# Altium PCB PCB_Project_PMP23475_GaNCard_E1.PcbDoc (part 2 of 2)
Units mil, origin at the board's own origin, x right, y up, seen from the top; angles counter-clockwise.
Board outline 1635 x 1330 mil, 6 copper layers (Top Layer, MidLayer1, MidLayer2, MidLayer3, MidLayer4, Bottom Layer), stack 78 mil thick; 80 components, 70 nets, 296 pads, 209 vias.
Unrouted connection lines stored in the file: 3.
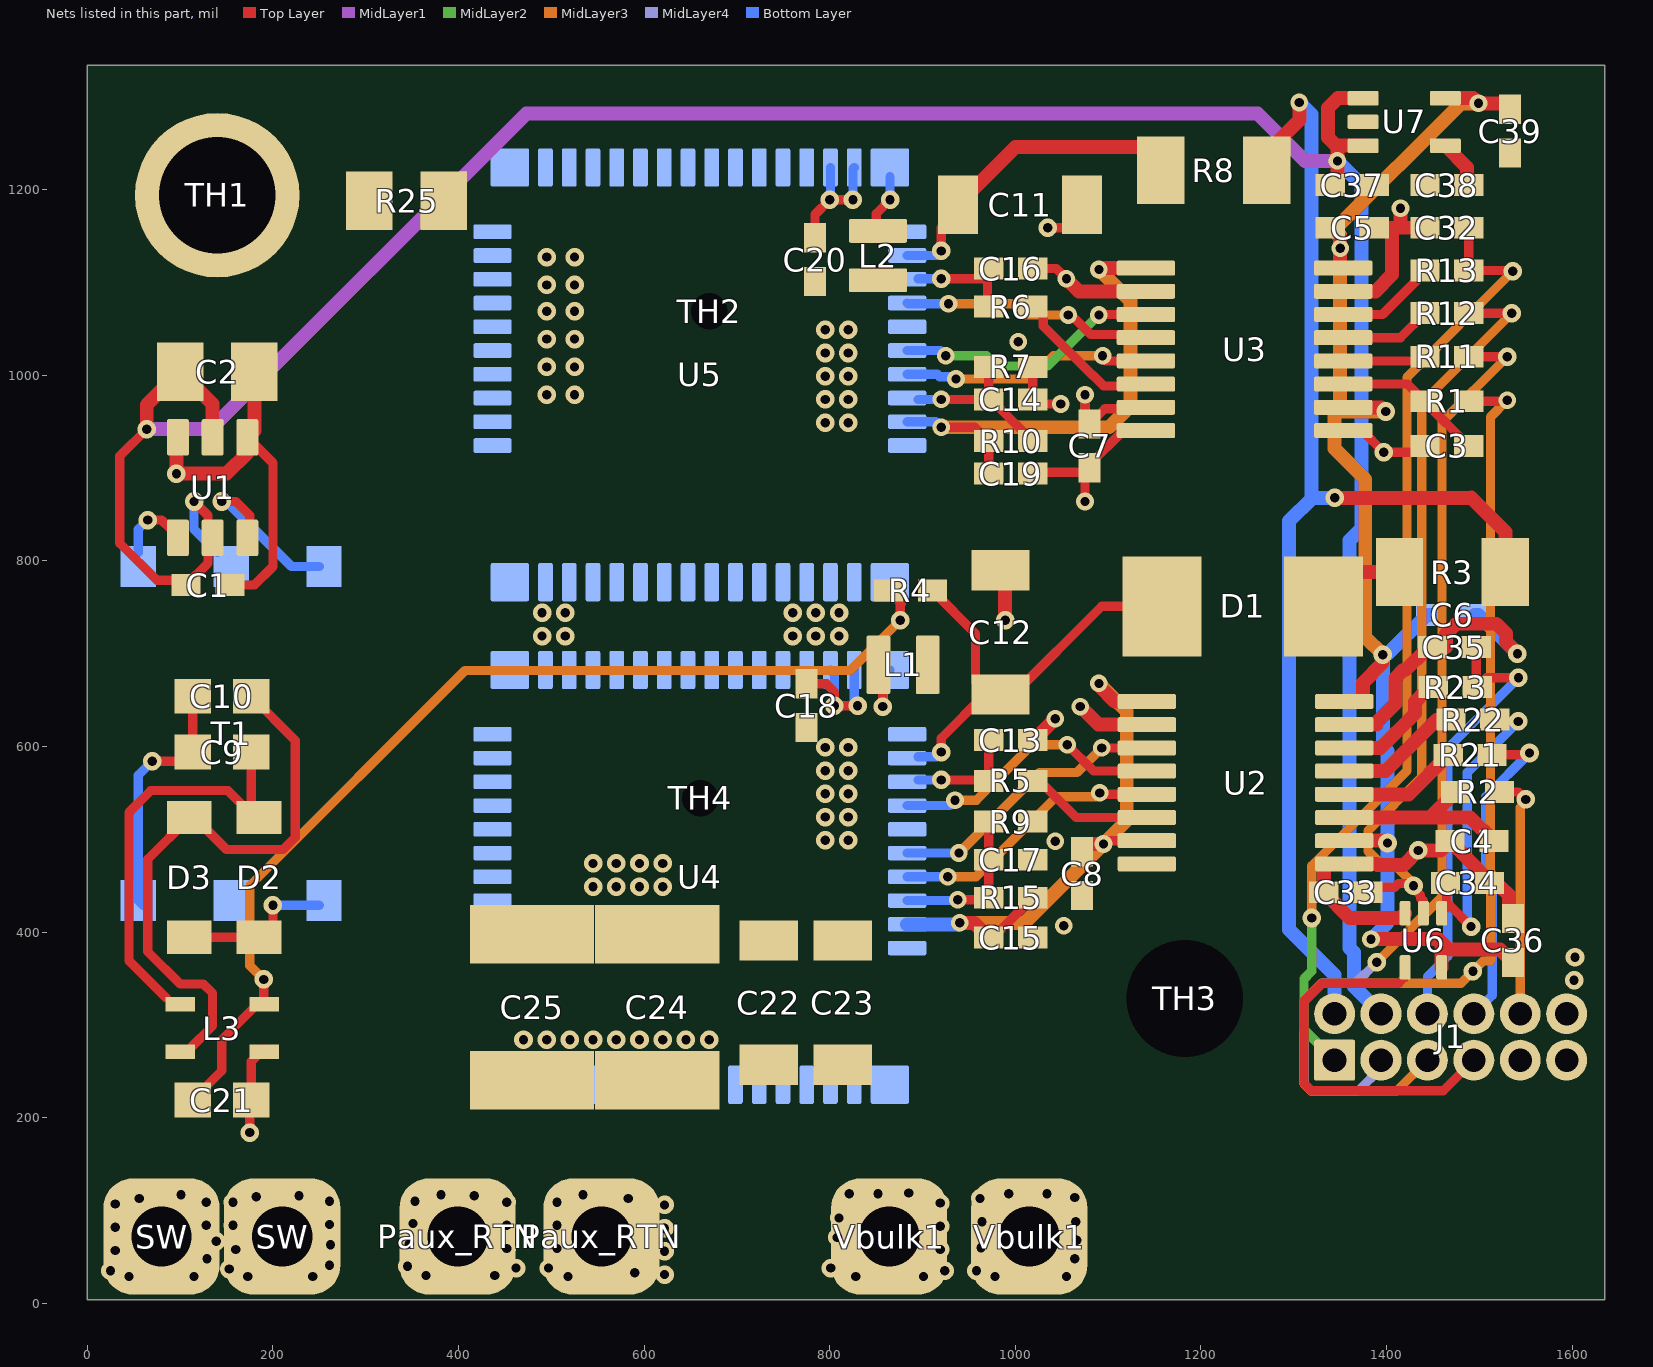
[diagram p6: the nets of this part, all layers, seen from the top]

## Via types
v1: diameter 20, hole 10, Top Layer to Bottom Layer, 174 vias
v2: diameter 19, hole 10, Top Layer to Bottom Layer, tented both sides, 35 vias

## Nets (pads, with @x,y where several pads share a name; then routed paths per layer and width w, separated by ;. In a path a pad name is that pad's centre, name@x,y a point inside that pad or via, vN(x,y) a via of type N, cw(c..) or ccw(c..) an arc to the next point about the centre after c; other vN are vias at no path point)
3.3V: C5.1 C6.1 C36.1 C39.2 U2.10 U2.16 U3.10 U3.16 U6.5 U7.5 | length 1624.1
  Top Layer w15: C5.1@1339.38,1159 1350,1148.38 v2(1350,1137) 1350,1118.8 U3.16@1353.3,1115.5 ; U3.10@1353.3,965.5 1394.5,965.5 v1(1399,961) ; U2.10@1354.3,498.5 1398.5,498.5 v1(1401,496) ; U2.16@1354.3,648.5 1373.85,648.5 1374.43,649.07 1374.43,668.63 1395.04,689.24 1395.04,698.04 v1(1396,699) ; v2(1383.15,392.23) 1383.48,392.56 1455.89,392.56 1467.14,381.31 1522.07,381.31 C36.1@1536,367.38 ; U6.5@1459.37,362 1459.37,389.08 ; U7.5@1463.29,1298.59 1493.41,1298.59 v2(1499,1293) 1526.62,1293 C39.2@1533,1286.62
  MidLayer3 w15: v1(1396,699) 1377,718 1377,888 1344,921 1344,960 1345,961 ; v1(1399,961) 1345,961 ; v2(1499,1293) 1480,1293 1344,1157 1350,1151 v2(1350,1137) 1350,966 1345,961
  Bottom Layer w15: v2(1383.15,392.23) 1401,410.08 v1(1401,496) 1401,595 1396,600 v1(1396,699) 1396.96,699.96 1401.66,699.96 1443.44,741.74 C6.1@1447.38,741.74
5V: C1.1 C2.1 C37.1 J1.4 T1.5 U1.2 U1.5 U7.1 U7.3 | length 3063
  Top Layer w10: v1(64,942) 35,913 35,819 75,779 C1.1@100,779 ; C1.1@106.38,774 130,797.62 U1.2@130,819 ; v1(115,864) 130,849 U1.2@130,839
  Top Layer w15: v1(64,942) 64,968 C2.1@100,1004 C2.1@101.5,1002.5 ; C2.1@118.5,985.5 135,969 U1.5@135,933.13 ; C37.1@1339.38,1205 1347,1212.62 v2(1347,1231) 1347,1243 1351.41,1247.41 ; U7.3@1374.71,1247.41 1351.41,1247.41 ; U7.1@1374.71,1298.59 1347.59,1298.59 1337,1288 1337,1256 1345.59,1247.41 1351.41,1247.41
  MidLayer1 w15: v1(64,942) 133,942 473,1282 1261,1282 1312,1231 v2(1347,1231)
  Bottom Layer w10: v1(115,864) 115,834 T1.5@140,809
  Bottom Layer w15: v2(1347,1231) 1373,1205 1373,835 1360.15,822.15 1360.15,382.7 1365,377.85 1365,341.27 1394,312.27 J1.4@1394,312
5V_H: C8.1 C15.2 R15.1 U2.1 U2.7 U4.51 | length 682.1
  Top Layer w10: C15.2@971.38,394 975.51,394 998.32,416.81 998.43,416.81 R15.1@1018.62,437 ; v2(1095,495) 1098.5,498.5 U2.7@1141.7,498.5
  Top Layer w15: v2(940,410) 955.38,410 C15.2@971.38,394 ; C8.1@1072,486.62 1080.38,495 v2(1095,495) ; v2(1090,668) 1090,665.55 1107.05,648.5 U2.1@1141.7,648.5
  MidLayer3 w15: v2(940,410) 1010,410 v2(1095,495) 1120,520 1120,638 v2(1090,668)
  Bottom Layer w10: v2@938.41,408.41 v2(940,410)
  Bottom Layer w15: U4.51@883.43,408.41 v2@938.41,408.41
5V_L: C7.2 C19.2 R10.1 U3.1 U3.7 U5.51 | length 649.9
  Top Layer w10: v2@925,944 956.38,944 R10.1@971.38,929 971.38,895.38 C19.2@970,894 ; C7.2@1075,954 v2(1075,979) ; C7.2@1080,947.62 1096.38,964 U3.7@1110,964
  Top Layer w15: v2(1090,1114) 1091.5,1115.5 U3.1@1140.7,1115.5
  MidLayer3 w10: 1075,944 v2(1075,979)
  MidLayer3 w15: v2(920,944) 1075,944 1101,944 1124,967 1124,1080 v2(1090,1114)
  Bottom Layer w10: U5.51@883.43,949.91 914.09,949.91 v2(920,944)
12V: J1.2 R3.1 R8.1 | length 1392.4
  Top Layer w15: R8.1@1271.09,1221 1271.09,1229 1260,1229 1306,1275 v2(1306,1294) v2@1306,1292.09 ; v1(1344,868) 1491.38,868 ; 1491.19,868.19 1491.38,868 ; R3.1@1528.09,788 1528.09,831.29 1491.38,868
  Bottom Layer w15: v2(1306,1294) 1319,1281 1319,867 1320,868 ; J1.2@1344,312 1344,353.9 1295,402.9 1295,843 1320,868 ; v1(1344,868) 1320,868
AGND: C1.2 C2.2 C3.2 C4.2 C5.2 C6.2 C32.2 C33.2 C34.2 C35.2 C36.2 C37.2 C38.2 C39.1 J1.9 J1.11 J1.12 U1.4 U1.6 U2.9 U2.15 U3.9 U3.15 U6.3 U7.2 | length 1440.8
  Top Layer w10: C1.2@155,774 180,774 200,794 200,905.54 U1.4@172.63,932.9 ; U3.9@1353.3,940.5 1373.5,940.5 v1(1397,917) 1434.38,917 C3.2@1441.38,924
  Top Layer w15: U1.6@97.6,933.13 96,931.54 v1(96,894) 150.12,894 172.63,916.51 172.63,932.9 180,940.27 C2.2@180,1004 ; U3.15@1353.3,1090.5 1387.95,1090.5 1406,1108.55 1406,1159 ; U2.15@1354.3,623.5 1388.95,623.5 1388.95,625.63 1409.45,646.13 1409.45,673.95 1418.24,682.74 1421.18,682.74 1441.13,702.69 1445.07,702.69 C35.2@1449.38,707 1464.19,707 1464.19,721.22 1475.28,732.31 1517.96,732.31 1528.57,721.7 1528.57,712.43 v1(1541,700) ; C5.2@1386.62,1160 1387.62,1159 1415,1159 ; v2(1415,1180) 1415,1159 ; U6.3@1420,420.27 1414.96,415.23 1360.15,415.23 C33.2@1332.38,443 1332.38,472.93 1332.95,473.5 1388.95,473.5 1389.95,472.5 1418.5,472.5 v1(1434,488) 1458.38,488 C4.2@1468.38,498 1504.62,461.76 C34.2@1504.62,453 ; C32.2@1440.38,1160 C32.2@1441.38,1159 1415,1159 ; C34.2@1510.62,453 1514.93,448.69 1522.9,448.69 1531.69,439.9 1531.69,418.93 C36.2@1536,414.62
  Bottom Layer w15: C6.2@1494.62,741.74 1499.26,741.74 v1(1541,700)
  other v1: 1602,348 1603,373
FAULT_HS: U2.4 U4.46 | length 297.3
  Top Layer w10: v2(1056,602) 1084.5,573.5 U2.4@1141.7,573.5
  MidLayer3 w10: v2(935,542) 958,542 1018,602 v2(1056,602)
  Bottom Layer w10: U4.46@883.43,536.36 929.36,536.36 v2(935,542)
FAULT_LS: U3.4 U5.46 | length 272.7
  Top Layer w10: v2(1057,1065) 1060.3,1065 1081.3,1044 1137.2,1044 U3.4@1140.7,1040.5
  MidLayer3 w10: v2(928,1077) 997.78,1077 1009.78,1065 v2(1057,1065)
  Bottom Layer w10: U5.46@883.43,1077.86 884.28,1077 v2(928,1077)
GaN_F: J1.7 U6.4 | length 424.4
  Top Layer w10: U6.4@1420,367.32 1419.09,366.41 1419.09,350.91 1413.24,345.05 1330.31,345.05 1310.95,325.69 1310.95,236.56 1318.56,228.95 1460.95,228.95 J1.7@1494,262
HS_FAULT: C34.1 R22.2 U6.1 | length 348.6
  Top Layer w10: C34.1@1457.38,453 1458.14,453 1464.95,446.19 1464.95,432.05 1468.05,428.95 ; U6.1@1459.37,420.27 1459.37,425.28 1460.28,426.19 1465.29,426.19 1468.05,428.95 ; v1(1491,406) 1468.05,428.95 ; R22.2@1516.62,629 1518.62,627 v1(1542,627)
  Bottom Layer w10: v1@1487,404 1487,572 v1(1542,627)
HS_PWM: J1.10 R2.1 | length 254
  Top Layer w10: R2.1@1521.62,551 1542,551 v1(1550,543)
  MidLayer3 w10: J1.10@1544,312 1544,534.29
HS_TEMP: J1.8 R21.2 | length 352.9
  Top Layer w10: R21.2@1513.62,591 1552,591 v1(1554,593)
  Bottom Layer w10: J1.8@1494,312 1514,332 1514,462 1507,469 1507,546 v1(1554,593)
HS_ZVS: C35.1 J1.6 R23.2 | length 493.2
  Top Layer w10: R23.2@1496.62,665 C35.1@1496.62,707 ; R23.2@1497.62,664 1507.64,674.02 v1(1542.04,674.02)
  Bottom Layer w10: J1.6@1444,312 1444,352 1466,374 1466,597.98 v1(1542.04,674.02)
HVBUS: C22.1 C23.1 C24.1 C25.1 U4.2 U4.3 U4.4 U4.5 U4.6 U4.7 U4.8 U4.9 U4.10 U4.11 U4.12 U4.13 U4.14 U4.15 Vbulk1.1
  other v1: 828,29 901,29 978,29 1055,29 924,35 958,35 801,38 1064,48 919,58 963,60 1066,68 808,71 919,83 964,88 1065,88 810,92 919,108 962,113 1064,114 821,118 852,118 993,118 1034,118 885,119 470,284 495,284 520,284 545,284 570,284 595,284 620,284 645,284 670,284
ISO_12V_H: C21.1 L3.2 R4.1 | length 1117.5
  Top Layer w10: C21.1@113.5,219 145,250.5 145,284 L3.2@180,319 ; L3.2@190,324 v1(190,349) ; R4.1@863.38,768 877.31,754.07 876,752.76 v1(876,736.02)
  MidLayer3 w10: v1(190,349) 175,364 175,450 407,682 821.98,682 v1(876,736.02)
LS_FAULT: C33.1 R12.2 U6.2 | length 844.3
  Top Layer w10: C33.1@1379.62,443 1384.94,448.32 1408.88,448.32 1412.88,452.32 1426.68,452.32 v1(1429,450) 1429,447.29 1436.63,439.66 1436.63,436.63 1439.69,433.58 U6.2@1439.69,420.27 ; R12.2@1488.62,1067 v1(1535,1067)
  MidLayer3 w10: v1(1429,450) 1429,452 1406,475 1392.3,475 1379.96,487.35 1379.96,509.33 1438,567.37 1438,970 v1(1535,1067)
LS_PWM: J1.5 R1.1 | length 1111.3
  Top Layer w10: R1.1@1488.62,972 1529,972 v2(1530,973)
  MidLayer3 w10: J1.5@1444,262 1410.95,228.95 1318.56,228.95 1310.95,236.56 1310.95,325.69 1330.31,345.05 1480.24,345.05 v1(1493,357.81) 1504.05,368.86 1512,368.86 1512,955 v2(1530,973)
LS_TEMP: J1.3 R11.2 | length 1041.9
  Top Layer w10: R11.2@1488.62,1020 v1(1530,1020)
  MidLayer3 w10: v1(1389.41,367.51) 1459.7,437.8 1459.7,949.7 v1(1530,1020)
  MidLayer4 w10: v1(1389.41,367.51) 1367.05,345.15 1330.41,345.15 1310.95,325.69 1310.95,236.56 1318.56,228.95 1369.44,228.95 1394,253.51 J1.3@1394,262
LS_ZVS: C32.1 J1.1 R13.2 | length 1050.7
  Top Layer w10: C32.1@1488.62,1159 R13.2@1488.62,1113 1535,1113 v1(1536,1112)
  MidLayer2 w10: v1(1319.5,415.19) 1319.5,358.04 1310.95,349.49 1310.95,295.05 J1.1@1344,262
  MidLayer3 w10: v1(1319.5,415.19) 1319.5,471.5 1422,574 1422,998 v1(1536,1112)
NC1: R25.2 TH1.1
NC2: TH2.1
NC3: TH3.1
NC4: TH4.1
NCT1: T1.2
NCU51: U4.1
NCU61: U5.1
NCU516: U4.16
NCU527: U4.27
NCU543: U4.43
NCU547: U4.47
NCU552: U4.52
NCU616: U5.16
NCU627: U5.27
NCU643: U5.43
NCU647: U5.47
NCU652: U5.52
NetC3_1: C3.1 R1.2 U3.11 | length 163.3
  Top Layer w10: U3.11@1353.3,990.5 1422.88,990.5 R1.2@1441.38,972 1441.38,971.24 C3.1@1488.62,924
NetC4_1: C4.1 R2.2 U2.11 | length 210.8
  Top Layer w15: U2.11@1354.3,523.5 1446.88,523.5 ; R2.2@1474.38,551 1446.88,523.5 ; C4.1@1515.62,498 1490.12,523.5 1446.88,523.5
NetC9_1: C9.1 D2.1 L3.3 | length 444.8
  Top Layer w10: L3.3@85,329 45,369 45,529 68.48,552.48 151.52,552.48 D2.1@176.5,527.5 ; C9.1@176.5,594 D2.1@176.5,527.5 ; D2.1@185,523.47 180.53,523.47 D2.1@176.5,527.5
NetC9_2: C9.2 C10.1 T1.3 | length 264.7
  Top Layer w10: v1(70,584) C9.2@110,584 ; C9.2@110,594 113.5,597.5 C10.1@113.5,654
  Bottom Layer w10: T1.3@60,429 T1.3@55,434 55,569 v1(70,584)
NetC10_2: C10.2 D3.2 L3.4 | length 601.4
  Top Layer w10: L3.4@110,274 135,299 135,334 125,344 100,344 65,379 65,478.47 D3.2@110,523.47 ; D3.2@130,509 150,489 211,489 224,502 224,606.5 C10.2@176.5,654
NetC11_1: C11.1 R8.2 U5.44 | length 349.6
  Top Layer w10: v1@922.5,1131.5 v1(920,1134) 920,1159 C11.1@930,1169 ; C11.1@938.07,1175.93 C11.1@938.07,1184
  Top Layer w15: C11.1@938.07,1184 1000.07,1246 1141,1246 1141,1236.91 R8.2@1156.91,1221
  Bottom Layer w10: U5.44@883.43,1129.04 915.04,1129.04 v1(920,1134)
NetC12_1: C12.1 D1.1 R4.2 U4.44 | length 529
  Top Layer w10: R4.2@910.62,768 957,721.62 957,669 969.93,656.07 C12.1@984,656.07 ; v1(920,594) 920,609 967.07,656.07 C12.1@984,656.07 ; D1.1@1129.99,723 D1.1@1157.99,751 1093,751 998.07,656.07 C12.1@984,656.07
  Bottom Layer w10: U4.44@895,589 915,589 v1(920,594)
NetC13_2: C13.2 R5.1 U4.45 | length 119.8
  Top Layer w10: v1(920,564) 970.38,564 R5.1@971.38,565 ; R5.1@971.38,563 R5.1@971.38,565 ; C13.2@971.38,606 R5.1@971.38,565
  Bottom Layer w10: U4.45@895,564 v1(920,564)
NetC14_2: C14.2 R7.2 R10.2 U5.50 | length 179.6
  Top Layer w10: v2(920,974) C14.2@971.38,974 ; R7.2@975,1009 971.38,1005.38 C14.2@971.38,974 ; R10.2@1018.62,929 975,972.62 975,974 C14.2@971.38,974
  Bottom Layer w10: U5.50@895,974 v2(920,974)
NetC16_2: C16.2 R6.2 U5.45 | length 116.6
  Top Layer w10: v1(920,1104) C16.2@970,1104 ; R6.2@970,1074 C16.2@970,1104 ; C16.2@971.38,1115 971.38,1105.38 C16.2@970,1104
  Bottom Layer w10: U5.45@895,1104 v1(920,1104)
NetC17_2: C17.2 R9.2 R15.2 U4.50 | length 171.2
  Top Layer w10: v2(938,435) 969.38,435 R15.2@971.38,437 C17.2@971.38,478 R9.2@971.38,519
  Bottom Layer w10: U4.50@883.43,434 937,434 v2(938,435)
NetC18_1: C18.1 U4.40 U4.41 | length 148.7
  Top Layer w10: C18.1@775,667.62 796.38,667.62 805,659 v1@805,649 ; v1(805,644) v1(830,644)
  Bottom Layer w10: U4.40@800.75,682.43 805,678.17 v1(805,644) ; U4.41@826.34,682.43 826.34,647.66 v1(830,644)
NetC20_1: C20.1 U5.40 U5.41 | length 140.1
  Top Layer w10: C20.1@784.19,1148.25 784.19,1173.19 v1(800,1189) 820,1189 v1@825,1184
  Bottom Layer w10: v1(800,1189) 800.75,1189.75 U5.40@800.75,1223.92 ; v1@825,1194 825,1222.58 U5.41@826.34,1223.92
  other v1: 825,1189
NetC38_1: C38.1 U7.4 | length 52.9
  Top Layer w15: U7.4@1463.29,1247.41 1486.62,1224.08 1486.62,1207 C38.1@1488.62,1205
NetD1_2: D1.2 R3.2 | length 97.2
  Top Layer w15: D1.2@1332.01,751 1369.01,788 R3.2@1413.91,788
NetD2_2: D2.2 D3.1 T1.1 | length 157.3
  Top Layer w10: D3.1@110,394.53 179.47,394.53 D2.2@180,394 ; D2.2@195,394 200,399 v1(200,429)
  Bottom Layer w10: v1(200,429) T1.1@250,429
NetL1_2: L1.2 U4.42 | length 88.9
  Top Layer w10: v1(857,643) 857,685.57 L1.2@859.43,688
  Bottom Layer w10: v1(857,643) 857,674.15 865,682.15 U4.42@864.72,682.43
NetL2_2: L2.2 U5.42 | length 56.2
  Top Layer w10: L2.2@850,1164 850,1174 v1(865,1189)
  Bottom Layer w10: v1(865,1189) U5.42@865,1214
NetR5_2: R5.2 U2.6 | length 138.7
  Top Layer w10: R5.2@1021.31,567.69 1065.5,523.5 U2.6@1141.7,523.5
NetR6_1: R6.1 U3.6 | length 166.5
  Top Layer w10: R6.1@1025,1074 R6.1@1018.62,1074 1030,1062.62 1030,1053 1083,1000 1083.7,1000 1095.2,988.5 U3.6@1137.7,988.5
NetR11_1: R11.1 U3.12 | length 89.9
  Top Layer w10: U3.12@1353.3,1015.5 1436.88,1015.5 R11.1@1441.38,1020
NetR12_1: R12.1 U3.13 | length 99.1
  Top Layer w10: U3.13@1353.3,1040.5 1414.88,1040.5 R12.1@1441.38,1067
NetR13_1: R13.1 U3.14 | length 108.7
  Top Layer w10: U3.14@1353.3,1065.5 1395.5,1065.5 1441.38,1111.38 R13.1@1441.38,1113
NetR21_1: R21.1 U2.12 | length 129.7
  Top Layer w15: U2.12@1354.3,548.5 1423.88,548.5 R21.1@1466.38,591
NetR22_1: R22.1 U2.13 | length 138.1
  Top Layer w15: U2.13@1354.3,573.5 1399.07,573.5 1454.57,629 R22.1@1469.38,629
NetR23_1: R23.1 U2.14 | length 130.7
  Top Layer w15: U2.14@1354.3,598.5 1393.65,598.5 1430.45,635.3 1430.45,648.01 1442.13,659.69 1446.07,659.69 R23.1@1450.38,664
NetT1_4: T1.4 U1.1 | length 68.3
  Top Layer w10: v1(65,844) 80,844 U1.1@90,834
  Bottom Layer w10: T1.4@55,809 55,834 v1(65,844)
NetT1_6: T1.6 U1.3 | length 180.2
  Top Layer w10: v1(145,864) 160,864 175,849 U1.3@175,839
  Bottom Layer w10: v1(145,864) 150,864 220,794 T1.6@250,794
PGND: C7.1 C11.2 C14.1 C16.1 C19.1 C20.2 C22.2 C23.2 C24.2 C25.2 L2.1 Paux_RTN.1 R7.1 R25.1 U3.2 U3.8 U5.17 U5.18 U5.19 U5.20 U5.21 U5.22 U5.23 U5.24 U5.25 U5.26 U5.28 U5.29 U5.30 U5.31 U5.32 U5.33 U5.34 U5.35 U5.36 U5.37 U5.38 U5.39 | length 371.2
  Top Layer w10: C14.1@1018.62,974 1018.62,1002.62 R7.1@1020,1004 ; C16.1@1018.62,1115 1044,1115 v2(1055,1104) ; C19.1@1025,899 1028.62,895.38 1075,895.38 v2(1075,864) ; C14.1@1025,974 1030,969 v2(1049,969) ; v1(1035,1159) C11.2@1055,1159 ; C7.1@1080,900.38 1080,904 1116.5,940.5 U3.8@1140.7,940.5
  Top Layer w15: v2(1055,1104) 1068.5,1090.5 U3.2@1140.7,1090.5
  other v1: 518,29 365,30 439,30 622,31 590,33 462,38 497,38 345,40 622,56 452,59 506,59 347,64 622,81 452,84 506,84 351,86 622,106 452,109 506,109 353,110 583,113 417,116 381,117 534,117 545,449 570,449 595,449 620,449 545,474 570,474 595,474 620,474 795,949 820,949 795,974 820,974 495,979 525,979 795,999 820,999 495,1009 525,1009 795,1024 820,1024 495,1039 525,1039 795,1049 820,1049 495,1069 525,1069 495,1097.39 525,1097.39 495,1127.39 525,1127.39
  other v2: 1003,1036
SW: C8.2 C12.2 C13.1 C15.1 C17.1 C18.2 C21.2 L1.1 L3.1 R9.1 SW.1 U2.2 U2.8 U4.17 U4.18 U4.19 U4.20 U4.21 U4.22 U4.23 U4.24 U4.25 U4.26 U4.28 U4.29 U4.30 U4.31 U4.32 U4.33 U4.34 U4.35 U4.36 U4.37 U4.38 U4.39 U5.2 U5.3 U5.4 U5.5 U5.6 U5.7 U5.8 U5.9 U5.10 U5.11 U5.12 U5.13 U5.14 U5.15 | length 260.3
  Top Layer w10: v1(175,184) C21.2@175,214 ; C21.2@176.5,219 176.5,260.5 L3.1@190,274
  Top Layer w15: C12.2@984,789.93 989,784.93 v1(989,736) ; C13.1@1018.62,607 1020,607 v2(1043,630) ; v2(1070,643) 1089.5,623.5 U2.2@1141.7,623.5
  other v1: 45,29 115,29 173,29 243,29 25,35 153,37 261,41 129,48 30,57 160,58 262,63 139,67 30,82 128,84 157,84 261,85 30,107 128,109 157,109 261,110 56,113 182,115 228,116 101,117 795,499 820,499 795,524 820,524 795,549 820,549 795,574 820,574 795,599 820,599 490,719 515,719 760,719 785,719 810,719 490,744 515,744 760,744 785,744 810,744
  other v2: 1052,407 1043,498
TEMP_HS: U2.5 U4.49 | length 296.3
  Top Layer w10: v2(1091,550) 1092.5,548.5 U2.5@1141.7,548.5
  MidLayer3 w10: v2(927,459.59) 957.59,459.59 1044,546 1087,546 v2(1091,550)
  Bottom Layer w10: U4.49@883.43,459.59 v2(927,459.59)
TEMP_LS: U3.5 U5.49 | length 273.2
  Top Layer w10: v2(1094,1021) 1094,1019 1097.5,1015.5 U3.5@1140.7,1015.5
  MidLayer3 w10: v2(936,996) 1016,996 1041,1021 v2(1094,1021)
  Bottom Layer w10: U5.49@883.43,1001.09 915.92,1001.09 918.51,998.5 933.5,998.5 v2(936,996)
ZVS_HS: U2.3 U4.48 | length 305.2
  Top Layer w10: v2(1093,598.5) U2.3@1141.7,598.5
  MidLayer3 w10: v2(939.18,485.18) 1026,572 1066.5,572 v2(1093,598.5)
  Bottom Layer w10: U4.48@883.43,485.18 v2(939.18,485.18)
ZVS_LS: U3.3 U5.48 | length 287.2
  Top Layer w10: v2(1090,1065) 1090.5,1065.5 U3.3@1140.7,1065.5
  MidLayer2 w10: v2(925,1021) 969,1021 980,1010 1035,1010 v2(1090,1065)
  Bottom Layer w10: U5.48@883.43,1026.68 919.32,1026.68 v2(925,1021)

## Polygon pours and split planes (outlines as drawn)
SW on Bottom Layer "NONET_L-01_P-001" (solid, pour order 442): 13,133 268,133 268,132 278,122 278,5.5 272.5,0 16,0 5,11 5,123
SW on Bottom Layer "Bottom Layer-SW 2" (solid, pour order 370): 0,154 0,-6 275.81,-6 275.81,154
HVBUS on Bottom Layer "MidLayer4-PGND" (solid, pour order 376): 440,219 465,194 660,194 701.54,152.46 702.78,0 1084,0 1084,220 985,319 460,319 440,299
HVBUS on Bottom Layer "Bottom Layer-Vbulk+" (solid, pour order 374): 875,154 875,-6 1040,-6 1040,154
PGND on Bottom Layer "Bottom Layer-PGND 1" (solid, pour order 372): 333.35,153 333.35,-18.77 647.35,-18.77 647.35,153
SW on Bottom Layer "Bottom Layer-SW" (solid, pour order 368): 940,794 910,824 372.69,824 372.69,654 930,654 940,664
SW on Bottom Layer "Bottom Layer-SW 1" (solid, pour order 366): 770,734 775,729 775,624 845,624 845,376.52 822.48,354 760,354 760,569 705,624 569.69,624 475,529.31 475,364 455,344 395,344 372.7,366.3 372.7,734
AGND on Bottom Layer "Bottom Layer-AGND" (solid, pour order 364): 1525,235 1525,274 1572,321 1572,389 1621,389 1621,235
PGND on Bottom Layer "Bottom Layer-PGND" (solid, pour order 362): 842.97,1164 800,1164 780,1184 780,1254 360,1254 360,874 842.97,874
HVBUS on Bottom Layer "Bottom Layer-NetC23_1" (solid, pour order 360): 900,264 845,319 355,319 355,209 902.13,209 900,211.13
PGND on Top Layer "Top Layer-PGND 2" (solid, pour order 388): 325,138 325,19.5 660,19.5 660,138
SW on Top Layer "Top Layer-SW 1" (solid, pour order 386): 3.52,161 3.52,1 272.5,1 272.5,161
HVBUS on Top Layer "MidLayer4-PGND" (solid, pour order 394): 1080,224 1043,261 1005,299 393,299 393,214 427,180 661,180 737,104 737,-6 1080,-6
AGND on Top Layer "Top Layer-AGND" (solid, pour order 382): 1474.27,164 1474.27,279.27 1600,405 1634.72,405 1634.65,164
PGND on Top Layer "Top Layer-No Net 3" (solid, pour order 438): 389,1220 400,1231 480,1231 541,1170 541,960 529,948 451,948 399,1000 399,1147 389,1157
NC1 on Top Layer "Top Layer-No Net 2" (solid, remove dead copper, pour order 436): 304,1215 248,1271 101,1271 69,1239 69,1151 109,1111 236,1111 253,1111 304,1162
SW on Top Layer "Top Layer-No Net" (solid, pour order 432): 1003,536 1033,536 1053,516 1053,466 1056,463 1089,463 1108,482 1173,482 1175,480 1175,460 1170,455 1123,455 1050,382 1003,382 1000,385 1000,404 1006,410 1033,410 1043,420 1043,452 1040,455 1004,455 997,462 997,530
SW on Top Layer "Top Layer-SW" (solid, pour order 392): 900,501 883,484 790,484 774.4,499.6 774.4,589.6 760,604 760,639 785,639 785,629 790,624 870,624 890,644 890,715.46 894.54,720 919,720 924,715 924,633 900,609
PGND on Top Layer "Top Layer-PGND 1" (solid, pour order 384): 775,1119 765,1109 765,934 785,914 850,914 875,939 875,1014 890,1029 995,1029 1000,1024 1000,964 1010,954 1050,954 1060,964 1060,1005 1007,1058 912,1058 885,1085 885,1113 879,1119
PGND on Top Layer "Top Layer-PGND" (solid, pour order 380): 846,418 840,424 750,424 700,497.27 419.19,497.27 389.19,467.27 389.19,377.27 407.61,358.85 839.85,358.85 846,365
HVBUS on Top Layer "Top Layer-NetC23_1" (solid, pour order 378): 1060,265 1026,299 399,299 399,196 1037,196 1060,219
AGND on Top Layer "Top Layer-No Net 1" (solid, pour order 434): 1371,1218 1383,1230 1395,1230 1398,1233 1398,1258 1392,1264 1358,1264 1356,1266 1356,1279 1360,1283 1493,1283 1513,1263 1538,1263 1546,1255 1546,1223 1544,1221 1513,1221 1486,1248 1486,1256 1481,1261 1441,1261 1437,1257 1437,1240 1459,1218 1459,1147 1455,1143 1375,1143 1371,1147
SW on MidLayer4 "NONET_L-01_P-001" (solid, pour order 444): 13,133 268,133 268,132 278,122 278,5.5 272.5,0 16,0 5,11 5,123
PGND on MidLayer4 "MidLayer4-PGND 2" (solid, pour order 404): 287.13,21 287.13,129.87 235,182 235,484 355,604 425,604 425,213.6 471.6,167 594,167 660,101 660,21
HVBUS on MidLayer4 "MidLayer4-PGND" (solid, pour order 406): 440,219 465,194 628,194 690,132 690,0 1085,0 1085,219 985,319 460,319 440,299
SW on MidLayer4 "MidLayer1-SW" (solid, pour order 402): 765,379 765,649 814,649 972,807 1155,807 1180,782 1180,454 1130,454 1035,359 785,359
PGND on MidLayer4 "MidLayer1-PGND" (solid, pour order 400): 785,919 825,879 925,879 961,843 1154,843 1179,868 1179,1207 1132,1254 825,1254 785,1214
PGND on MidLayer4 "MidLayer4-PGND 1" (solid, pour order 398): 395,1209 347.5,1161.5 347.5,401.5 399,350 725,350 743,368 743,691 702.5,731.5 702.5,891.5 752.5,941.5 752.5,1176.5 720,1209
AGND on MidLayer4 "MidLayer1-AGND" (solid, pour order 396): 1291,163 1310,182 1310,185.05 1310,1224 1275,1259 1250,1259 1250,1329 1530,1329 1623,1236 1623,23 1250,23 1250,163
HVBUS on MidLayer2 "MidLayer4-PGND" (solid, pour order 416): 440,219 465,194 643,194 713,124 713,-6 1086,-6 1086,218 985,319 460,319 440,299
PGND on MidLayer2 "NONET_L-01_P-001" (solid, pour order 445): 339.5,134 644,134 644,1 342.5,1 331.5,12 331.5,124
SW on MidLayer2 "MidLayer3-SW 1" (solid, pour order 414): 276.22,158 275.39,0 228,0 0,0 0,656 228,656 396,824 793.33,824 825,800.25 825,676 472,676 276.22,480.22
AGND on MidLayer2 "MidLayer1-AGND" (solid, pour order 412): 1291,163 1310,182 1310,185.05 1310,1224 1275,1259 1116.54,1259 1116.54,1329 1530,1329 1622,1237 1622,19 1245,19 1245,163
AGND on MidLayer2 "MidLayer2-AGND" (solid, pour order 410): 1130,1324 155,1324 0,1169 0,732 153,732 220,799 220,1004 475,1259 1130,1259
SW on MidLayer2 "MidLayer1-SW" (solid, pour order 408): 750,394 750,649 840,649 998,807 1156,807 1180,783 1180,454 1130,454 1035,359 785,359
HVBUS on MidLayer1 "MIDLAYER1_HVBUS_P447" (solid, pour order 447): 713,139 666.02,185.98 561.02,185.98 461,286 461,343 744.5,343 936,151.5 1087,151.5 1087,0.5 713,0.5
SW on MidLayer1 "NONET_L-01_P-001" (solid, pour order 441): 13,133 268,133 268,132 278,122 278,5.5 272.5,0 16,0 5,11 5,123
AGND on MidLayer1 "MidLayer1-AGND" (solid, pour order 422): 1290,163 1291,163 1310,182 1310,1224 1260,1274 1116.54,1274 1116.54,1329 1530,1329 1624,1235 1624,-2 1245,-2 1245,163
PGND on MidLayer1 "MidLayer2-PGND" (solid, pour order 426): 473,1182 243,952 243,345.78 243,260.32 243,186.81 306.31,123.5 306.31,25.07 300.41,20 641,20 641,157 552,157 429,280 429,870 511,952 738,952 738,1182
PGND on MidLayer1 "MIDLAYER1_PGND_P439" (solid, pour order 439): 350.62,153 641,153 641,2 354.6,2
AGND on MidLayer1 "MidLayer2-AGND" (solid, remove dead copper, pour order 424): 1265,1324 145,1324 0,1179 0,732 193,732 220,759 220,954 540,1274 1265,1274
SW on MidLayer1 "MidLayer1-SW" (solid, pour order 420): 750,394 750,649 840,649 998,807 1152,807 1180,779 1180,454 1130,454 1035,359 785,359
PGND on MidLayer1 "MidLayer1-PGND" (solid, pour order 418): 785,919 825,879 925,879 961,843 1152,843 1180,871 1180,1188 1154,1214 785,1214
PGND on MidLayer3 "NONET_L-01_P-001" (solid, pour order 446): 339.5,134 644,134 644,1 342.5,1 331.5,12 331.5,124
SW on MidLayer3 "NONET_L-01_P-001" (solid, pour order 443): 13,133 268,133 268,132 278,122 278,5.5 272.5,0 16,0 5,11 5,123
HVBUS on MidLayer3 "MidLayer4-PGND" (solid, pour order 430): 440,219 465,194 648,194 690,152 690,-6 1080,-6 1080,224 985,319 460,319 440,299

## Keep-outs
Keep-Out Layer:
  lines w7: 0,0 160,0 235,0 395,0 877,0 1037,0 1245,0 1635,0 1635,1334 0,1334 0,0
  text ".Layer_Name" at -831,-2217.49 h60

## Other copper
Top Layer:
  text ".Layer_Name" at -831,-2218 h60
Bottom Layer:
  text ".Layer_Name" at 576,1456 h60

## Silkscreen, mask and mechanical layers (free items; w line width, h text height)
Top Overlay:
  lines w10: 245,514 265,514 ; 965,754 965,774
  text "PMP40988_GaN" at 270,1269 h40
  text "Rev. E1" at 491,1212 h40
  text ".Layer_Name" at -831,-2217.49 h60
Bottom Overlay:
  text ".Layer_Name" at -831,-2217.49 h60
Top Paste:
  text ".Layer_Name" at -831,-2217.49 h60
Bottom Paste:
  text ".Layer_Name" at -831,-2217.49 h60
Top Solder:
  text ".Layer_Name" at -831,-2217.49 h60
  text ".Layer_Name" at -831,-2217.49 h60
Bottom Solder:
  text ".Layer_Name" at -831,-2217.49 h60
Drill Guide:
  text ".Layer_Name" at -831,-2217.49 h60
M1 Board Outline:
  the board outline again, w10
  text ".Layer_Name" at -831,-2217.49 h60
M2 Board Dimensions:
  rectangle: -1408,-1634 -1283,-1509
  rectangle: -1283,-1759 -908,-1634
  lines w7: -1408,-1634 -408,-1634 ; -1283,-1759 -1283,-1509 ; -1158,-1759 -1158,-1509 ; -908,-1759 -908,-1509 ; -658,-1759 -658,-1509 ; -1408,-1759 -408,-1759 -408,-1509 -1408,-1509 -1408,-1759
  text ".Layer_Name" at -831,-2217.49 h60
M3 3D STEP Top:
  text ".Layer_Name" at -831,-2217.49 h60
M4 3D STEP Bottom:
  text ".Layer_Name" at -831,-2217.49 h60
M5 Assembly Top:
  lines w10: -1700,-2289.17 4900,-2289.17 ; -1700,-2085.83 4902,-2085.83 ; -1700,-1882.5 -1700,-2492.5 2305,-2492.5 4902,-2492.5 4902,-1882.5 -1699.5,-1882.5 -1699.5,-2492.5 -124,-2492.5 ; 765,-2492.5 765,-1882.5 ; 2032,-2085.83 2032,-1882.5 ; 2872,-2085.83 2872,-1882.5 ; 3494,-2499 3494,-2296.17
  text "COMPONENTS MARKED 'DNP' SHOULD NOT BE POPULATED." at -254.5,-1677.5 h60
  text "ASSEMBLY VARIANT:" at -255,-1793 h60
  text ".VariantName" at 781,-1793 h60
  text "PCB VIEWED FROM TOP SIDE" at -1636.5,-2014.67 h60
  text "BOARD #:" at 840,-2014.67 h60
  text ".PRJ_Number" at 1385.5,-2014.67 h60
  text "REV:" at 2230,-2014.67 h60
  text ".PCB_Rev" at 2521.5,-2014.67 h60
  text "SVN REV:" at 3068,-2014.67 h60
  text ".VersionControl_RevNumber" at 3574,-2014.67 h60
  text "TID #:" at 840,-2218 h60
  text ".TID" at 1385.5,-2218 h60
  text "PLOT NAME =" at -1636.5,-2423.34 h60
  text ".plot_File_Name" at -831,-2423.34 h60
  text "GENERATED    :" at 842,-2423.34 h60
  text ".Print_Date" at 1711.5,-2423.34 h60
  text ".Print_Time" at 2440.5,-2423.34 h60
  text "TEXAS INSTRUMENTS" at 3705,-2423.34 h60
M6 Assembly Bottom:
  lines w10: -1700.5,-2086.33 4901.5,-2086.33 ; -1698.5,-2289.67 4901.5,-2289.67 ; -292.5,-2499.5 -292.5,-2296.67 ; 329.5,-2086.33 329.5,-1883 ; 1169.5,-2086.33 1169.5,-1883 ; 2436.5,-2493 2436.5,-1883 ; 3325.5,-2493 4901,-2493 4901,-1883 -1700.5,-1883 -1700.5,-2493 896.5,-2493 4901.5,-2493 4901.5,-1883
  text "COMPONENTS MARKED 'DNP' SHOULD NOT BE POPULATED." at 4694,-1677 h60
  text ".VariantName" at 3650,-1793 h60
  text "ASSEMBLY VARIANT:" at 4689,-1793 h60
  text ".VersionControl_RevNumber" at -372.5,-2015.17 h60
  text "SVN REV:" at 133.5,-2015.17 h60
  text ".PCB_Rev" at 680,-2015.17 h60
  text "REV:" at 971.5,-2015.17 h60
  text ".PRJ_Number" at 1816,-2015.17 h60
  text "BOARD #:" at 2361.5,-2015.17 h60
  text "PCB VIEWED FROM BOTTOM SIDE" at 4838,-2015.17 h60
  text ".TID" at 1816,-2218.5 h60
  text "TID #:" at 2361.5,-2218.5 h60
  text "TEXAS INSTRUMENTS" at -503.5,-2423.84 h60
  text ".Print_Time" at 761,-2423.84 h60
  text ".Print_Date" at 1490,-2423.84 h60
  text "GENERATED    :" at 2359.5,-2423.84 h60
  text ".plot_File_Name" at 4032.5,-2423.84 h60
  text "PLOT NAME =" at 4838,-2423.84 h60
M9 Title Sheet:
  drawing of 57 lines, arcs and shapes, not listed
  text "1" at -668.16,6677.5 h70
  text "2" at 1827.5,6677.5 h70
  text "3" at 4316.84,6677.5 h70
  text "4" at 6823.51,6677.5 h70
  text "5" at 9322.5,6677.5 h70
  text "6" at 11827.5,6677.5 h70
  text "A" at -1824.5,5534.5 h70
  text "A" at 12975.5,5534.5 h70
  text "B" at -1824.5,3154.5 h70
  text "B" at 12975.5,3154.5 h70
  text "C" at -1824.5,779.5 h70
  text "C" at 12975.5,779.5 h70
  text "PROJECT TITLE:" at 9935.5,-1081.5 h45
  text ".PRJ_Title" at 9985.5,-1214.83 h70
  text "DESIGNED FOR:" at 9935.5,-1382.5 h45
  text ".PRJ_Customer" at 9985.5,-1522.5 h70
  text "D" at -1824.5,-1590.5 h70
  text "D" at 12975.5,-1590.5 h70
  text "FILE NAME:" at 9935.5,-1682.5 h45
  text ".PCB_File_Name_No_Path" at 9985.5,-1802.5 h70
  text "Texas Instruments (TI) and/or its licensors do not warrant the accuracy or completeness of this specification" at 4966,-1964.34 h45
  text "ENGINEER:" at 9935.5,-1972.5 h45
  text "LAYOUT BY:" at 11440.5,-1972.5 h45
  text "or any information contained therein. TI and/or its licensors do not warrant that this design will meet" at 4921.01,-2077 h45
  text ".PRJ_Engineer" at 9985.5,-2127.49 h70
  text ".PCB_Layout" at 11491,-2127.49 h70
  text "the specifications, will be suitable for your application or fit for any particular purpose, or will operate in" at 4921.01,-2189.67 h45
  text ".Layer_Name" at -831,-2217.49 h60
  text "ALTIUM DESIGNER VERSION:" at 11440.5,-2282.5 h45
  text "an implementation. TI and/or its licensors do not warrant that the design is production worthy. You should" at 4921.01,-2302.33 h45
  text "completely validate and test your design implementation to confirm the system functionality for your application." at 4966,-2415 h45
  text ".print_Scale" at 9985.5,-2415.83 h70
  text ".Application_BuildNumber" at 11491,-2415.83 h70
  text "1" at -668.16,-2622.5 h70
  text "2" at 1827.5,-2622.5 h70
  text "3" at 4316.84,-2622.5 h70
  text "4" at 6823.51,-2622.5 h70
  text "5" at 9322.5,-2622.5 h70
  text "6" at 11827.5,-2622.5 h70
M10 Fab Notes:
  drawing of 189 lines, arcs and shapes, not listed
  text "DESIGN INFORMATION" at 10974.02,4997.17 h60
  text "MIN. TRACK WIDTH:" at 10329.46,4865.05 h60
  text "8" at 11425.7,4865.05 h60
  text "MIL" at 11580.46,4865.05 h60
  text "MIN. CLEARANCE:" at 10329.46,4740.92 h60
  text "0.2" at 11365.7,4740.93 h60
  text "mm" at 11580.46,4740.92 h60
  text "MIN. VIA PAD SIZE:" at 10329.46,4616.8 h60
  text "24" at 11395.71,4616.8 h60
  text "MIL" at 11580.46,4616.8 h60
  text "0.05mm (2MIL)" at 11024.46,4486.9 h60
  text "MINIMUM ANNULAR RING" at 10000.23,4478.67 h60
  text "EXTERNAL" at 11732.46,4478.67 h60
  text "PER" at 10200.23,4368.55 h60
  text "IPC-D-275 CLASS 2 LEVEL C" at 10420.23,4368.54 h60
  text "MIL, HOLES" at 11908.46,4268.07 h60
  text "+/-" at 11516,4259.48 h60
  text "+/-" at 12370,4259.48 h60
  text "REGISTRATION TOLERANCES:" at 10000.23,4258.42 h60
  text "METAL" at 11200,4258.42 h60
  text "5" at 11776.2,4258.42 h60
  text "3" at 12609.2,4258.42 h60
  text "MIL" at 12725.46,4258.42 h60
  text "HOLE SIZE TOLERANCE (UNLESS OTHERWISE SPECIFIED):" at 10000.23,4160.1 h60
  text "+/-" at 12370,4157.23 h60
  text "3" at 12609.2,4156.17 h60
  text "MIL" at 12725.46,4156.17 h60
  text "MATERIAL:" at 9925.46,4018.52 h60
  text "FR-4 High Tg" at 10911.9,3890 h60
  text "X" at 10767.46,3882.01 h60
  text "FR-408" at 10346.46,3877.49 h60
  text "OTHER" at 11834.46,3877.49 h60
  text "62 MIL (1.6mm) +/-10%" at 10666.56,3734.46 h60
  text "X" at 10546.46,3732.01 h60
  text "THICKNESS:" at 10000.23,3726.24 h60
  text "OTHER" at 11951.46,3726.24 h60
  text "TOLERANCE:" at 10000.23,3587.92 h60
  text "X" at 10848.46,3587.92 h60
  text "ANSI IPC-6012 TYPE 3 CLASS 2" at 11026.48,3587.92 h60
  text "OTHER +/-" at 11026.46,3443.73 h60
  text "BOW & TWIST:" at 10000.23,3298.54 h60
  text "X" at 10848.46,3298.54 h60
  text "ANSI IPC-6012 TYPE 3 CLASS 2" at 11026.48,3298.54 h60
  text "OTHER +/-" at 11026.46,3151.85 h60
  text "DRILLING:" at 9925.46,3021.23 h60
  text "NC_DRILL FILES" at 11686.46,2916.04 h60
  text "REFERENCE:" at 10000.23,2912.1 h60
  text "X" at 10657.46,2912.01 h60
  text "AS SHOWN" at 10835.46,2912.1 h60
  text "X" at 11558.46,2912.1 h60
  text "OTHER" at 11984.46,2769.85 h60
  text "PTH COPPER THICKNESS:" at 9999.91,2766.32 h60
  text "X" at 11139.14,2766.32 h60
  text "20-30 um" at 11267.14,2766.32 h60
  text "BOARD FINISH:" at 9925.46,2618.73 h60
  text "SILKSCREEN:" at 10080.68,2508.6 h60
  text "X" at 11038.46,2508.6 h60
  text "TOP" at 11155.46,2508.6 h60
  text "X" at 11548.46,2508.6 h60
  text "BOTTOM" at 11666.46,2508.6 h60
  text "SILKSCREEN COLOR:" at 10080.68,2353.41 h60
  text "X" at 11037.46,2353.41 h60
  text "WHITE" at 11155.46,2353.41 h60
  text "OTHER" at 11666.46,2353.41 h60
  text "X" at 11168.46,2209.96 h60
  text "GREEN" at 11286.46,2209.96 h60
  text "OTHER" at 11904.46,2209.96 h60
  text "SOLDER RESIST COLOR:" at 10080.68,2203.1 h60
  text "X" at 11168.46,2055.71 h60
  text "MATTE" at 11286.46,2055.71 h60
  text "SEMI-GLOSS" at 11904,2055.07 h60
  text "IMMERSION GOLD (ENIG)" at 10986.46,1882.94 h60
  text "ENEPIG" at 12324,1875.72 h60
  text "SURFACE FINISH:" at 9925.46,1874.72 h60
  text "X" at 10808.46,1874.72 h60
  text "IMM. TIN/SILVER OR EQUIV" at 10255,1737.4 h60
  text "OTHER" at 11686.46,1733.47 h60
  text "ARRAY/PANEL:" at 9925.46,1578.09 h60
  text "CUT AND TRIM PER M1 BOARD OUTLINE" at 10986.46,1569.87 h60
  text "N.C. ROUTE" at 10986.46,1433.9 h60
  text "X" at 11674.46,1433.9 h60
  text "V. SCORE" at 11852.46,1433.9 h60
  text "CERTIFICATION:" at 9925.46,1304.77 h60
  text "MATERIALS AND WORKMANSHIP FOR ALL PCBS" at 10650.46,1304.77 h60
  text "TO MEET OR EXCEED THE REQUIREMENTS OF:" at 10650.46,1210.71 h60
  text "X" at 10287.97,1082.08 h60
  text "ANSI IPC-A-600F CLASS ->" at 10415.96,1082.08 h60
  text "X" at 12063.97,1082.08 h60
  text "2" at 12173.96,1082.08 h60
  text "1" at 11858.96,1080.58 h60
  text "3" at 12527.96,1080.58 h60
  text "X" at 11099.97,934.39 h60
  text "RoHS" at 11227.96,934.39 h60
  text "OTHER" at 11872.36,934.39 h60
  text "PER ORDER" at 12269.42,934.39 h60
  text "ALL BOARDS MUST MEET OR EXCEED UL94-V0 REQUIREMENTS." at 9953,780.57 h60
  text "PCB MUST BEAR THE UL94V-0 UL REGISTERED MATERIAL ID NUMBER" at 9953,664.5 h60
  text "ADDITIONAL REQUIREMENTS:" at 9925.46,495.08 h60
  text "MICROSECTION:" at 10000.23,387.95 h60
  text "YES" at 10905.96,387.95 h60
  text "REQUIRED" at 11767.46,243.62 h60
  text "BARE BOARD ELEC. TEST:" at 10000.23,240.76 h60
  text "NONE" at 11305.96,240.76 h60
  text "X" at 11649.46,240.76 h60
  text "PER ORDER" at 12359.46,240.76 h60
  text "XX MIL VIAS REQUIRE NON-CONDUCTIVE FILL AND PLANARIZE" at 10168.38,35.82 h59
  text "XX MIL VIAS REQUIRE CONDUCTIVE FILL AND PLANARIZE" at 10176.38,-68.16 h60
  text "OUTER XX MIL TRACES REQUIRE 50 OHM SINGLE-ENDED IMPEDANCE" at 10175.39,-231.54 h58
  text "LAYER 2 & 3 (INNER LAYERS) XX MIL WIDE, XX MIL SPACE / TRACES REQUIRE 100 OHM DIFFERENTIAL IMPEDANCE" at 10167.39,-467.26 h60
  text ".Layer_Name" at -831,-2217.49 h60
M11 Gerber Information:
  lines w10: -1700,-2289.17 4900,-2289.17 ; -1700,-2085.83 4902,-2085.83 ; -1700,-1882.5 -1700,-2492.5 2305,-2492.5 4902,-2492.5 4902,-1882.5 -1699.5,-1882.5 -1699.5,-2492.5 -124,-2492.5 ; 765,-2492.5 765,-1882.5 ; 2032,-2085.83 2032,-1882.5 ; 2872,-2085.83 2872,-1882.5 ; 3494,-2499 3494,-2296.17
  text "ALL ARTWORK VIEWED FROM TOP SIDE" at -1636.5,-2014.67 h60
  text "BOARD #:" at 840,-2014.67 h60
  text ".PRJ_Number" at 1385.5,-2014.67 h60
  text "REV:" at 2230,-2014.67 h60
  text ".PCB_Rev" at 2521.5,-2014.67 h60
  text "SVN REV:" at 3068,-2014.67 h60
  text ".VersionControl_RevNumber" at 3574,-2014.67 h60
  text "LAYER NAME =" at -1636.5,-2217.49 h60
  text "TID #:" at 840,-2218 h60
  text ".TID" at 1385.5,-2218 h60
  text "PLOT NAME =" at -1636.5,-2423.34 h60
  text ".plot_File_Name" at -831,-2423.34 h60
  text "GENERATED    :" at 842,-2423.34 h60
  text ".Print_Date" at 1711.5,-2423.34 h60
  text ".Print_Time" at 2440.5,-2423.34 h60
  text "TEXAS INSTRUMENTS" at 3705,-2423.34 h60
M12 Stackup:
  drawing of 7403 lines, arcs and shapes, not listed
  text "Layer" at 8399.84,6493.5 h60
  text "Name" at 8809.76,6493.5 h60
  text "Material" at 9739.5,6493.5 h60
  text "Thickness" at 10599.27,6493.5 h60
  text "Constant" at 11249.1,6493.5 h60
  text "Board Layer Stack" at 11818.96,6493.5 h60
  text "Board Layer Stack" at 12938.65,6493.5 h60
  text "Board Layer Stack" at 14058.33,6493.5 h60
  text "Board Layer Stack" at 15178.01,6493.5 h60
  text "Board Layer Stack" at 16297.7,6493.5 h60
  text "Board Layer Stack" at 17417.38,6493.5 h60
  text "Board Layer Stack" at 18537.06,6493.5 h60
  text "Board Layer Stack" at 19656.74,6493.5 h60
  text "Board Layer Stack" at 20776.43,6493.5 h60
  text "Board Layer Stack" at 21896.11,6493.5 h60
  text "Board Layer Stack" at 23015.79,6493.5 h60
  text "Board Layer Stack" at 24135.48,6493.5 h60
  text "Board Layer Stack" at 25255.16,6493.5 h60
  text "Board Layer Stack" at 26374.84,6493.5 h60
  text "Board Layer Stack" at 27494.53,6493.5 h60
  text "Top Overlay" at 8809.76,6373.5 h60
  text "Top Solder" at 8809.76,6253.5 h60
  text "Solder Resist" at 9739.5,6253.5 h60
  text "0.40mil" at 10599.27,6253.5 h60
  text "3.5" at 11249.1,6253.5 h60
  text "1" at 8399.84,6133.5 h60
  text "Top Layer" at 8809.76,6133.5 h60
  text "2.80mil" at 10599.27,6133.5 h60
  text "Dielectric 1" at 8809.76,6013.5 h60
  text "FR-4 High Tg" at 9739.5,6013.5 h60
  text "4.60mil" at 10599.27,6013.5 h60
  text "4.2" at 11249.1,6013.5 h60
  text "2" at 8399.84,5893.5 h60
  text "MidLayer1" at 8809.76,5893.5 h60
  text "2.80mil" at 10599.27,5893.5 h60
  text "Dielectric 2" at 8809.76,5773.5 h60
  text "FR-4 High Tg" at 9739.5,5773.5 h60
  text "23.70mil" at 10599.27,5773.5 h60
  text "4.2" at 11249.1,5773.5 h60
  text "3" at 8399.84,5653.5 h60
  text "MidLayer2" at 8809.76,5653.5 h60
  text "2.80mil" at 10599.27,5653.5 h60
  text "4.6" at 8809.76,5533.5 h60
  text "FR-4 High Tg" at 9739.5,5533.5 h60
  text "4.60mil" at 10599.27,5533.5 h60
  text "4.2" at 11249.1,5533.5 h60
  text "4" at 8399.84,5413.5 h60
  text "MidLayer3" at 8809.76,5413.5 h60
  text "2.80mil" at 10599.27,5413.5 h60
  text "Dielectric 4" at 8809.76,5293.5 h60
  text "23.70mil" at 10599.27,5293.5 h60
  text "4.2" at 11249.1,5293.5 h60
  text "5" at 8399.84,5173.5 h60
  text "MidLayer4" at 8809.76,5173.5 h60
  text "2.80mil" at 10599.27,5173.5 h60
  text "Dielectric 5" at 8809.76,5053.5 h60
  text "4.60mil" at 10599.27,5053.5 h60
  text "4.2" at 11249.1,5053.5 h60
  text "6" at 8399.84,4933.5 h60
  text "Bottom Layer" at 8809.76,4933.5 h60
  text "2.80mil" at 10599.27,4933.5 h60
  text "Bottom Solder" at 8809.76,4813.5 h60
  text "Solder Resist" at 9739.5,4813.5 h60
  text "0.40mil" at 10599.27,4813.5 h60
  text "3.5" at 11249.1,4813.5 h60
  text "Bottom Overlay" at 8809.76,4693.5 h60
  text ".Layer_Name" at -831,-2217.49 h60
M13 Component Bodies Top:
  text ".Layer_Name" at -831,-2217.49 h60
M14 Component Bodies Bottom:
  text ".Layer_Name" at -831,-2217.49 h60
M15 Courtyards Top:
  text ".Layer_Name" at -831,-2217.49 h60
M16 Courtyards Bottom:
  text ".Layer_Name" at -831,-2217.49 h60
Drill Drawing:
  circle w10: c3955.72,1404 r27.63
  lines w10: 3928.09,1500.7 3955.72,1514.51 3983.34,1500.7 3969.53,1528.32 3983.34,1555.95 3955.72,1542.14 3928.09,1555.95 3941.9,1528.32 3928.09,1500.7 ; 3928.09,1625.02 3983.34,1625.02 3983.34,1680.27 3928.09,1680.27 3928.09,1625.02 ; 3928.09,1763.15 3941.9,1763.15 3955.72,1749.34 3969.53,1763.15 3983.34,1763.15 3969.53,1776.96 3983.34,1790.78 3969.53,1790.78 3955.72,1804.59 3941.9,1790.78 3928.09,1790.78 3941.9,1776.96 3928.09,1763.15 ; 3928.09,1928.91 3983.34,1928.91 3955.72,1873.66 3928.09,1928.91
  lines w12: 3878,1339.08 7109.49,1339.08 ; 3878,1960.68 7109.49,1960.68 ; 4215.86,1214.76 4215.86,2085 ; 4547.86,1214.76 4547.86,2085 ; 5184.43,1214.76 5184.43,2085 ; 5443.57,1214.76 5443.57,2085 ; 5818.72,1214.76 5818.72,2085 ; 6543.05,1214.76 6543.05,2085 ; 3878,1214.76 7109.49,1214.76 7109.49,2085 3878,2085 3878,1214.76
  text "Symbol" at 3952.59,1997.98 h72
  text "Quantity" at 4253.16,1997.98 h72
  text "Finished Hole Size" at 4585.16,1997.98 h72
  text "Plated" at 5221.72,1997.98 h72
  text "Hole Type" at 5480.86,1997.98 h72
  text "Drill Layer Pair" at 5856.02,1997.98 h72
  text "Hole Tolerance" at 6580.35,1997.98 h72
  text "209" at 4253.16,1873.66 h60
  text "10.00mil (0.254mm)" at 4585.16,1873.66 h60
  text "PTH" at 5221.72,1873.66 h60
  text "Round" at 5480.86,1873.66 h60
  text "Top Layer - Bottom Layer" at 5856.02,1873.66 h60
  text "12" at 4253.16,1749.34 h60
  text "25.59mil (0.650mm)" at 4585.16,1749.34 h60
  text "PTH" at 5221.72,1749.34 h60
  text "Round" at 5480.86,1749.34 h60
  text "Top Layer - Bottom Layer" at 5856.02,1749.34 h60
  text "2" at 4253.16,1625.02 h60
  text "39.37mil (1.000mm)" at 4585.16,1625.02 h60
  text "PTH" at 5221.72,1625.02 h60
  text "Round" at 5480.86,1625.02 h60
  text "Top Layer - Bottom Layer" at 5856.02,1625.02 h60
  text "6" at 4253.16,1500.7 h60
  text "64.96mil (1.650mm)" at 4585.16,1500.7 h60
  text "PTH" at 5221.72,1500.7 h60
  text "Round" at 5480.86,1500.7 h60
  text "Top Layer - Bottom Layer" at 5856.02,1500.7 h60
  text "2" at 4253.16,1376.38 h60
  text "125.98mil (3.200mm)" at 4585.16,1376.38 h60
  text "PTH" at 5221.72,1376.38 h60
  text "Round" at 5480.86,1376.38 h60
  text "Top Layer - Bottom Layer" at 5856.02,1376.38 h60
  text "231 Total" at 4253.16,1252.06 h60
  text ".Layer_Name" at -831,-2217.49 h60
M17 Embedded Cavity:
  text ".Layer_Name" at -831,-2217.49 h60
M18 Embedded Assembly:
  text ".Layer_Name" at -831,-2217.49 h60
M19 Embedded Keepout:
  text ".Layer_Name" at -831,-2217.49 h60

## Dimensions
-1408,-1759 to -408,-1759 on M2 Board Dimensions
0,1334 to 1635,1334 on M2 Board Dimensions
